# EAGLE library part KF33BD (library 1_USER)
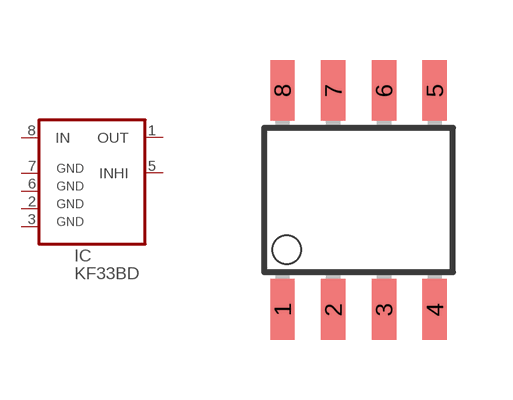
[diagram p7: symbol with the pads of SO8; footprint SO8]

Designator prefix IC

## KF33BD  [SO8]
1  OUT  out
2  GND_2  pwr
3  GND_3  pwr
5  INHI  in
6  GND_6  pwr
7  GND_7  pwr
8  IN  in

## Footprint SO8 (pad centres in mm)
smd 0.61 x 1.524: 1 -1.27,-2.743; 2 0,-2.743; 3 1.27,-2.743; 4 2.54,-2.743; 5 2.54,2.743; 6 1.27,2.743; 7 0,2.743; 8 -1.27,2.743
